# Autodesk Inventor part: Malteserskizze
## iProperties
Created: 2004-11
Part Number: Malteserskizze
Document SubType Name: Modeling
Designer: PALME
Manufacturer: Standard
Standards Organization: Custom
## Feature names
1. Extrusion1
